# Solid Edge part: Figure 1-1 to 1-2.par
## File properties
Author: CADCIM
Template: normal.par
Last saved by: TIET
Revision: 15
Application: Solid Edge
Accuracy: 0.99
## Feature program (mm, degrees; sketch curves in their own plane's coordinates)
sketch for "unnamed Protrusion 1" plane through (0, 0, 0) normal (0, 0, 1) x-axis (1, 0, 0)
  line (-63.0032, 49) -> (-56, -71)
  line (-56, -71) -> (56, -71)
  line (56, -71) -> (63.0032, 49)
  line (63.0032, 49) -> (0, 54)
  line (0, 54) -> (-63.0032, 49)
  dimension (linear) = 56
  dimension (linear) = 56
extrude "unnamed Protrusion 1" add finite 4 along +normal
fillet "Round_1" radius 15
sketch for "ExtrudedProtrusion_3" plane through (0, -8.5, 0) normal (0, 0, -1) x-axis (-1, 0, 0)
extrude "ExtrudedProtrusion_3" add finite 12 along -normal
pattern "unnamed Pattern 1" of "ExtrudedProtrusion_3"
pattern "unnamed Pattern 2"
sketch for "unnamed Protrusion 2" plane through (-1.0316, 2.3101, 4) normal (0, 0, 1) x-axis (-1, 0, 0)
extrude "unnamed Protrusion 2" add finite 5 along +normal
sketch for "Hole_22" plane through (40.9331, -54.9887, 12) normal (0, 0, 1) x-axis (1, 0, 0)
  hole centre (-0.4331, -0.0113) bore radius 4.5
hole "Hole_22" diameter 9 through  CounterBoreDepth = 5 mm
pattern "unnamed Pattern 3" of "Hole_22"
hole "unnamed Hole 1" through
hole "unnamed Hole 2" through
hole "unnamed Hole 3" through
sketch for "Hole_29" plane through (-1.0316, -6.1899, 9) normal (0, 0, 1) x-axis (1, 0, 0)
  hole centre (0, 0) bore radius 11
hole "Hole_29" diameter 22 through
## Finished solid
Body 1: solid body, 34 faces, 55 edges, 18 vertices.
  Faces by surface: cylinder 18, plane 16
  Edges by curve: circle 36, line 19
Bounding box of the edges (mm): 124.346 x 125.000 x 12.000, from (-62.1729, -71, 0) to (62.1729, 54, 12).
Cylindrical faces by radius (mm): R4.5 x4, R7.5 x4, R10.7006 x4, R11 x1, R15 x4, R20 x1
Planar faces by outward normal: +z 10, -y 1, -z 1, oblique 4
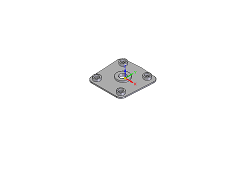
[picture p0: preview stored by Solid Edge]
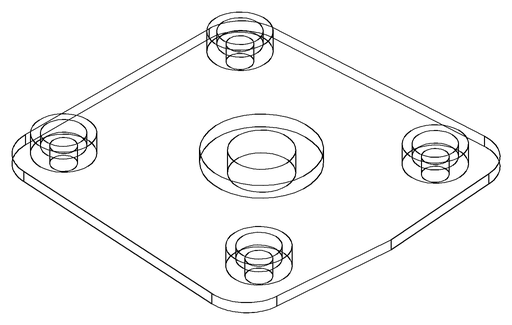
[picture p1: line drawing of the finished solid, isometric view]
